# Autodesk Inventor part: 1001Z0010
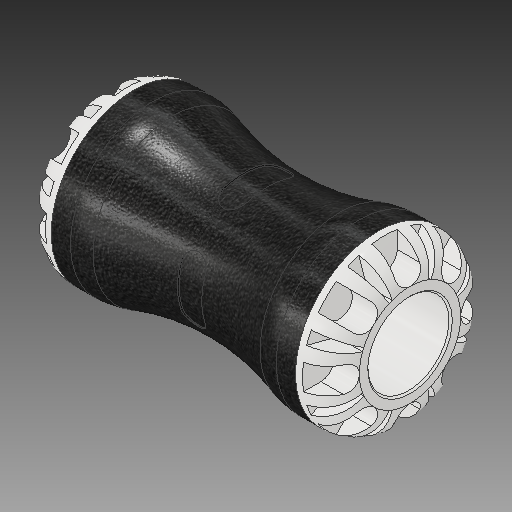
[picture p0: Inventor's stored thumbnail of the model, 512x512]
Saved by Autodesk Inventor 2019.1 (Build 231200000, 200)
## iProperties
Created: 2016-12
Part Number: 1001Z0010
Material: PVC-Piping
Description: PLASSON COUPLER 1''CTS x 1''CTS SERIES 1
Document SubType Name: Modeling
Designer: KIM
Mass: 95.2094 g
Surface Area: 200.83 cm^2
Volume: 68.0067 cm^3
Density: 1.4 g/cm^3
Appearance: White
ILogicFactory: False
Author: KIM
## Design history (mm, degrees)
derived "1001Z.ipt"
feature "Solid1::1001Z.ipt"
tag "TaggingFeature1"
body "Solid1"
other parameters: "d2" = 53.848, "d4" = 2.37083, "d11" = 8.9398, "d13" = 8.9398, "d14" = 0, "d16" = 360 deg, "d18" = 8 deg, "d19" = 0.569, "d20" = 8 deg, "d21" = 0.569, "d23" = 0, "d25" = 360 deg, "d27" = 23.1648, "d28" = 7.1125, "d29" = 8.535, "d30" = 8.535, "d31" = 0, "d33" = 0, "d37" = 21.59, "d38" = 0.57912, "d43" = 3.55625, "d44" = 28.45, "d45" = 21.59, "d46" = 46.3296, "d47" = 57.912, "d48" = 107.95, "d50" = 360 deg, "d54" = 0.5, "d_" = 28.45, "E_" = 57.912, "H_" = 107.95, "l_" = 53.848, "d12" = 35.5625, "d42" = 57.912, "d52" = 11.17475
